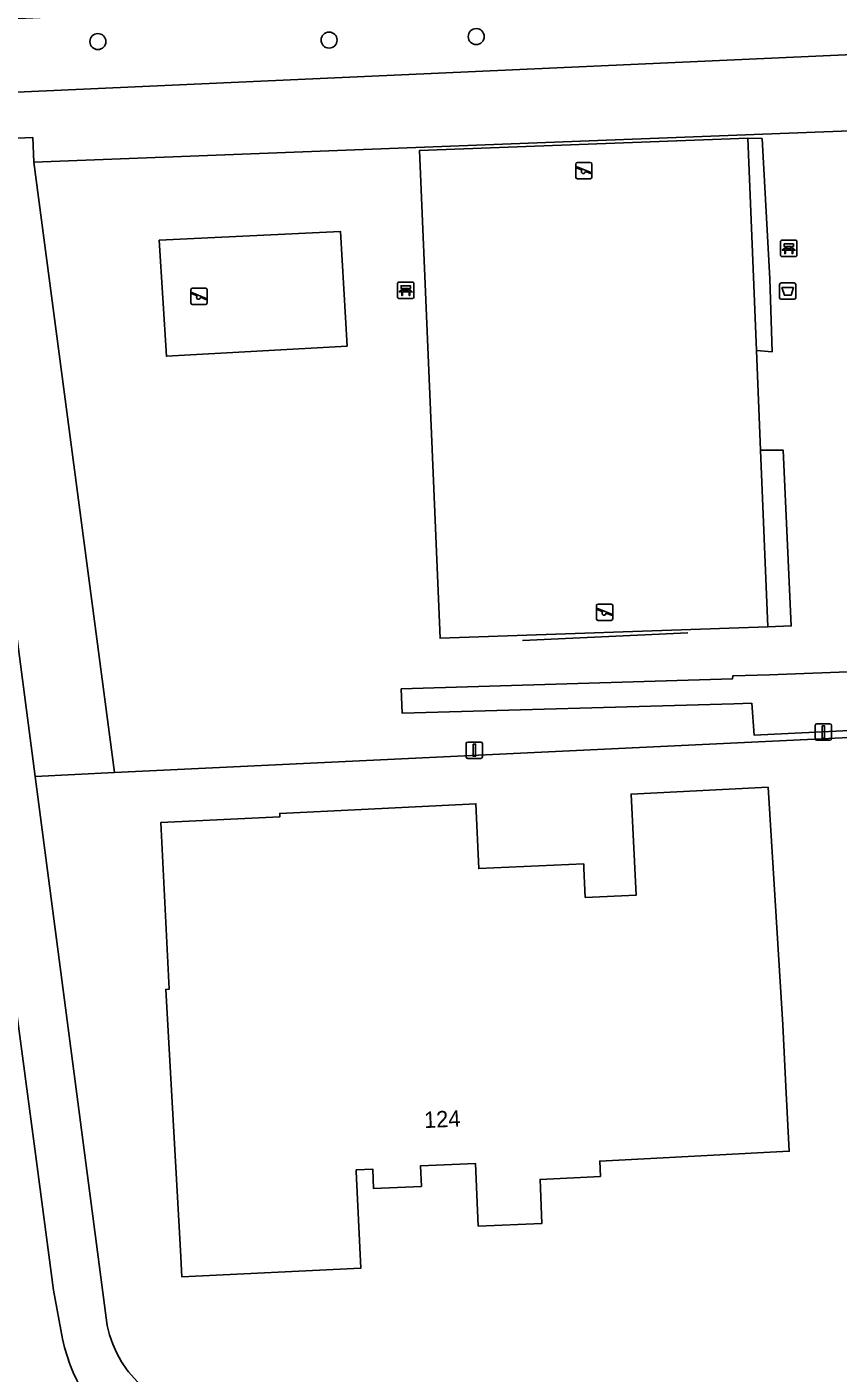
# Model space of a CAD drawing. Extents: x 161084 to 161928, y 385354 to 386522.
# Drawn here: x 161207.1 to 161256.7, y 385753.3 to 385835.6 of the extents above; entities that cross this region are included whole.
import ezdxf

# ---------------------------------------------------------------- set-up
doc = ezdxf.new("R2010")
doc.units = 0
for name, color, linetype in [('IMGEO_Afvalbak', 7, 'Continuous'), ('IMGEO_Bank', 7, 'Continuous'), ('IMGEO_Boom', 7, 'Continuous'), ('IMGEO_Erf', 7, 'Continuous'), ('IMGEO_Fietspad_gesloten', 7, 'Continuous'), ('IMGEO_Groenvoorziening', 7, 'Continuous'), ('IMGEO_Hek', 7, 'Continuous'), ('IMGEO_Lichtmast', 7, 'Continuous'), ('IMGEO_Pand', 7, 'Continuous'), ('IMGEO_Pand_nummerreeks', 7, 'Continuous'), ('IMGEO_Speelvoorziening', 7, 'Continuous'), ('IMGEO_Terreindeel_gesloten', 7, 'Continuous'), ('IMGEO_Terreindeel_onvherhard', 7, 'Continuous'), ('IMGEO_Voetpad_open', 7, 'Continuous')]:
    doc.layers.add(name, color=color, linetype=linetype)

msp = doc.modelspace()

# ---------------------------------------------------------------- linework, layer by layer
at = {"layer": 'IMGEO_Afvalbak'}
for p, q in [((161253.102, 385819.03), (161253.102, 385819.83)), ((161253.102, 385819.83), (161253.102, 385819.03)), ((161253.202, 385819.93), (161253.992, 385819.93)), ((161253.992, 385819.93), (161253.202, 385819.93)), ((161254.092, 385819.83), (161254.092, 385819.03)), ((161254.092, 385819.03), (161254.092, 385819.83)), ((161253.992, 385818.93), (161253.202, 385818.93)), ((161253.202, 385818.93), (161253.992, 385818.93))]:
    msp.add_line(p, q, dxfattribs=at)
msp.add_lwpolyline([(161253.245, 385819.644), (161253.949, 385819.644), (161253.8, 385819.174), (161253.394, 385819.174), (161253.245, 385819.644)], dxfattribs=at)
for centre, start, end in [((161253.202, 385819.83), 90, 180), ((161253.202, 385819.83), 90, 180), ((161253.992, 385819.83), 0, 90), ((161253.992, 385819.83), 360, 90), ((161253.202, 385819.03), 180, 270), ((161253.202, 385819.03), 180, 270), ((161253.992, 385819.03), 270, 0), ((161253.992, 385819.03), 270, 0)]:
    msp.add_arc(centre, 0.1, start, end, dxfattribs=at)
at = {"layer": 'IMGEO_Bank'}
for p, q in [((161253.161, 385821.616), (161253.161, 385822.457)), ((161253.161, 385822.457), (161253.161, 385821.616)), ((161253.236, 385822.541), (161254.077, 385822.541)), ((161254.077, 385822.541), (161253.236, 385822.541)), ((161253.858, 385821.939), (161253.465, 385821.939)), ((161253.47, 385822.047), (161253.47, 385822.153)), ((161253.514, 385822.153), (161253.514, 385822.047)), ((161253.802, 385822.159), (161253.52, 385822.159)), ((161253.52, 385822.041), (161253.802, 385822.041)), ((161253.808, 385822.047), (161253.808, 385822.153)), ((161253.852, 385822.153), (161253.852, 385822.047)), ((161254.161, 385822.466), (161254.161, 385821.625)), ((161254.161, 385821.625), (161254.161, 385822.466)), ((161254.086, 385821.541), (161253.245, 385821.541)), ((161253.245, 385821.541), (161254.086, 385821.541)), ((161229.73, 385819.057), (161229.73, 385819.898)), ((161229.73, 385819.898), (161229.73, 385819.057)), ((161229.805, 385819.982), (161230.646, 385819.982)), ((161230.646, 385819.982), (161229.805, 385819.982)), ((161230.039, 385819.488), (161230.039, 385819.594)), ((161230.083, 385819.594), (161230.083, 385819.488)), ((161230.371, 385819.6), (161230.089, 385819.6)), ((161230.089, 385819.482), (161230.371, 385819.482)), ((161230.377, 385819.488), (161230.377, 385819.594)), ((161230.421, 385819.594), (161230.421, 385819.488)), ((161230.73, 385819.907), (161230.73, 385819.066)), ((161230.73, 385819.066), (161230.73, 385819.907)), ((161230.655, 385818.982), (161229.814, 385818.982)), ((161229.814, 385818.982), (161230.655, 385818.982)), ((161230.427, 385819.38), (161230.034, 385819.38))]:
    msp.add_line(p, q, dxfattribs=at)
for points in [[(161253.408, 385821.939), (161253.266, 385821.939), (161253.378, 385822.041), (161253.464, 385822.041)], [(161253.464, 385822.159), (161253.378, 385822.159), (161253.378, 385822.32), (161253.941, 385822.32), (161253.941, 385822.159), (161253.858, 385822.159)], [(161253.458, 385821.932), (161253.458, 385821.725), (161253.415, 385821.725), (161253.415, 385821.932)], [(161253.858, 385822.041), (161253.941, 385822.041), (161254.053, 385821.939), (161253.914, 385821.939)], [(161253.908, 385821.932), (161253.908, 385821.725), (161253.864, 385821.725), (161253.864, 385821.932)], [(161229.977, 385819.38), (161229.835, 385819.38), (161229.947, 385819.482), (161230.033, 385819.482)], [(161230.033, 385819.6), (161229.947, 385819.6), (161229.947, 385819.761), (161230.51, 385819.761), (161230.51, 385819.6), (161230.427, 385819.6)], [(161230.427, 385819.482), (161230.51, 385819.482), (161230.622, 385819.38), (161230.483, 385819.38)], [(161230.027, 385819.373), (161230.027, 385819.166), (161229.984, 385819.166), (161229.984, 385819.373)], [(161230.477, 385819.373), (161230.477, 385819.166), (161230.433, 385819.166), (161230.433, 385819.373)]]:
    msp.add_lwpolyline(points, dxfattribs=at)
for centre, radius, start, end in [((161253.239, 385822.463), 0.0779, 92.4484, 184.28452), ((161253.239, 385822.463), 0.0779, 92.4484, 184.28452), ((161253.408, 385821.932), 0.00671, 2.89567, 87.10433), ((161253.465, 385821.932), 0.00671, 92.89567, 177.10433), ((161253.463, 385822.152), 0.00671, 2.89567, 87.10433), ((161253.463, 385822.048), 0.00671, 272.89567, 357.10433), ((161253.52, 385822.152), 0.00671, 92.89567, 177.10433), ((161253.52, 385822.048), 0.00671, 182.89567, 267.10433), ((161253.802, 385822.152), 0.00671, 2.89567, 87.10433), ((161253.802, 385822.048), 0.00671, 272.89567, 357.10433), ((161253.859, 385822.152), 0.00671, 92.89567, 177.10433), ((161253.859, 385822.048), 0.00671, 182.89567, 267.10433), ((161253.857, 385821.932), 0.00671, 2.89567, 87.10433), ((161253.914, 385821.932), 0.00671, 92.89567, 177.10433), ((161254.083, 385822.463), 0.0779, 2.4484, 94.28452), ((161254.083, 385822.463), 0.0779, 2.4484, 94.28452), ((161253.239, 385821.619), 0.0779, 182.4484, 274.28452), ((161253.239, 385821.619), 0.0779, 182.4484, 274.28452), ((161254.083, 385821.619), 0.0779, 272.4484, 4.28452), ((161254.083, 385821.619), 0.0779, 272.4484, 4.28452), ((161229.808, 385819.904), 0.0779, 92.4484, 184.28452), ((161229.808, 385819.904), 0.0779, 92.4484, 184.28452), ((161230.032, 385819.593), 0.00671, 2.89567, 87.10433), ((161230.032, 385819.489), 0.00671, 272.89567, 357.10433), ((161230.089, 385819.593), 0.00671, 92.89567, 177.10433), ((161230.089, 385819.489), 0.00671, 182.89567, 267.10433), ((161230.371, 385819.593), 0.00671, 2.89567, 87.10433), ((161230.371, 385819.489), 0.00671, 272.89567, 357.10433), ((161230.428, 385819.593), 0.00671, 92.89567, 177.10433), ((161230.428, 385819.489), 0.00671, 182.89567, 267.10433), ((161230.652, 385819.904), 0.0779, 2.4484, 94.28452), ((161230.652, 385819.904), 0.0779, 2.4484, 94.28452), ((161229.808, 385819.06), 0.0779, 182.4484, 274.28452), ((161229.808, 385819.06), 0.0779, 182.4484, 274.28452), ((161229.977, 385819.373), 0.00671, 2.89567, 87.10433), ((161230.034, 385819.373), 0.00671, 92.89567, 177.10433), ((161230.426, 385819.373), 0.00671, 2.89567, 87.10433), ((161230.483, 385819.373), 0.00671, 92.89567, 177.10433), ((161230.652, 385819.06), 0.0779, 272.4484, 4.28452), ((161230.652, 385819.06), 0.0779, 272.4484, 4.28452)]:
    msp.add_arc(centre, radius, start, end, dxfattribs=at)
at = {"layer": 'IMGEO_Boom'}
for centre in [(161211.394, 385834.688), (161225.538, 385834.781), (161234.541, 385834.99)]:
    msp.add_circle(centre, 0.489, dxfattribs=at)
at = {"layer": 'IMGEO_Erf'}
msp.add_lwpolyline([(161272.857, 385792.894), (161255.66, 385792.058), (161212.404, 385789.993), (161207.561, 385789.762), (161211.966, 385756.196), (161212.108, 385755.611), (161212.302, 385755.04), (161212.546, 385754.49), (161212.838, 385753.963), (161213.176, 385753.465), (161213.26, 385753.354), (161214.348, 385752.155)], dxfattribs=at)
msp.add_lwpolyline([(161234.664, 385762.266), (161234.497, 385766.092), (161231.128, 385765.946), (161231.182, 385764.692), (161228.259, 385764.563), (161228.206, 385765.755), (161227.197, 385765.706), (161227.202, 385765.606), (161227.486, 385759.696), (161216.52, 385759.168), (161216.441, 385760.775), (161215.546, 385776.741), (161215.746, 385776.751), (161215.241, 385786.94), (161222.534, 385787.299), (161222.524, 385787.498), (161227.518, 385787.744), (161234.52, 385788.09), (161234.695, 385784.122), (161241.117, 385784.406), (161241.129, 385784.12), (161241.207, 385782.36), (161244.322, 385782.491), (161244.015, 385788.683), (161252.394, 385789.097), (161253.303, 385774.578), (161253.484, 385770.805), (161253.689, 385766.848), (161244.045, 385766.345), (161242.098, 385766.243), (161242.133, 385765.306), (161238.447, 385765.122), (161238.469, 385764.583), (161238.557, 385762.435)], close=True, dxfattribs=at)
at = {"layer": 'IMGEO_Fietspad_gesloten'}
msp.add_lwpolyline([(161209.233, 385755.378), (161208.683, 385758.357), (161207.529, 385766.988), (161203.904, 385794.069)], dxfattribs=at)
msp.add_arc((161219.815, 385757.617), 10.816, 191.94693, 237.44684, dxfattribs=at)
at = {"layer": 'IMGEO_Groenvoorziening'}
for points in [[(161278.406, 385834.825), (161278.27, 385839.356), (161201.511, 385835.864), (161202.461, 385828.626), (161204.969, 385828.722), (161204.604, 385831.503)], [(161278.406, 385834.825), (161204.604, 385831.503), (161204.969, 385828.722), (161207.416, 385828.815), (161207.473, 385827.316), (161252.603, 385829.039), (161275.084, 385829.897), (161278.756, 385829.729)], [(161276.948, 385796.915), (161280.478, 385797.085), (161278.756, 385829.729), (161275.084, 385829.897), (161252.603, 385829.039), (161207.473, 385827.316), (161212.404, 385789.993), (161255.66, 385792.058), (161272.857, 385792.894), (161272.85, 385793.331), (161251.543, 385792.29), (161251.394, 385794.229), (161250.306, 385794.194), (161230.001, 385793.63), (161229.95, 385795.109), (161250.223, 385795.729), (161250.244, 385795.918), (161252.491, 385795.977)], [(161212.404, 385789.993), (161207.473, 385827.316), (161207.416, 385828.815), (161204.969, 385828.722), (161202.461, 385828.626), (161207.561, 385789.762)], [(161231.074, 385828.031), (161251.149, 385828.784), (161252.028, 385828.761), (161252.494, 385820.183), (161252.649, 385815.719), (161251.684, 385815.798), (161251.936, 385809.7), (161253.324, 385809.7), (161253.81, 385798.965), (161252.381, 385798.901), (161232.329, 385798.205)], [(161251.149, 385828.784), (161251.684, 385815.798), (161252.649, 385815.719), (161252.494, 385820.183), (161252.028, 385828.761)], [(161215.589, 385815.449), (161215.147, 385822.541), (161226.24, 385823.075), (161226.642, 385816.069)], [(161252.381, 385798.901), (161253.81, 385798.965), (161253.324, 385809.7), (161251.936, 385809.7)]]:
    msp.add_lwpolyline(points, close=True, dxfattribs=at)
at = {"layer": 'IMGEO_Hek'}
for points in [[(161252.603, 385829.039), (161275.084, 385829.897)], [(161207.473, 385827.316), (161252.603, 385829.039)], [(161212.404, 385789.993), (161207.473, 385827.316)], [(161247.495, 385798.546), (161237.365, 385798.075)], [(161255.66, 385792.058), (161272.857, 385792.894)], [(161255.66, 385792.058), (161212.404, 385789.993)], [(161212.404, 385789.993), (161207.561, 385789.762)]]:
    msp.add_lwpolyline(points, dxfattribs=at)
at = {"layer": 'IMGEO_Lichtmast'}
for p, q in [((161255.286, 385792.074), (161255.286, 385792.874)), ((161255.286, 385792.874), (161255.286, 385792.074)), ((161255.386, 385792.974), (161256.176, 385792.974)), ((161256.176, 385792.974), (161255.386, 385792.974)), ((161256.276, 385792.874), (161256.276, 385792.074)), ((161256.276, 385792.074), (161256.276, 385792.874)), ((161233.926, 385790.964), (161233.926, 385791.764)), ((161233.926, 385791.764), (161233.926, 385790.964)), ((161234.026, 385791.864), (161234.816, 385791.864)), ((161234.816, 385791.864), (161234.026, 385791.864)), ((161234.916, 385791.764), (161234.916, 385790.964)), ((161234.916, 385790.964), (161234.916, 385791.764)), ((161256.176, 385791.974), (161255.386, 385791.974)), ((161255.386, 385791.974), (161256.176, 385791.974)), ((161234.816, 385790.864), (161234.026, 385790.864)), ((161234.026, 385790.864), (161234.816, 385790.864))]:
    msp.add_line(p, q, dxfattribs=at)
for points in [[(161255.706, 385792.849), (161255.856, 385792.849), (161255.856, 385792.099), (161255.706, 385792.099), (161255.706, 385792.849)], [(161234.346, 385791.739), (161234.496, 385791.739), (161234.496, 385790.989), (161234.346, 385790.989), (161234.346, 385791.739)]]:
    msp.add_lwpolyline(points, dxfattribs=at)
for centre, start, end in [((161255.386, 385792.874), 90, 180), ((161255.386, 385792.874), 90, 180), ((161256.176, 385792.874), 0, 90), ((161256.176, 385792.874), 360, 90), ((161234.026, 385791.764), 90, 180), ((161234.026, 385791.764), 90, 180), ((161234.816, 385791.764), 0, 90), ((161234.816, 385791.764), 360, 90), ((161255.386, 385792.074), 180, 270), ((161255.386, 385792.074), 180, 270), ((161256.176, 385792.074), 270, 0), ((161256.176, 385792.074), 270, 0), ((161234.026, 385790.964), 180, 270), ((161234.026, 385790.964), 180, 270), ((161234.816, 385790.964), 270, 0), ((161234.816, 385790.964), 270, 0)]:
    msp.add_arc(centre, 0.1, start, end, dxfattribs=at)
at = {"layer": 'IMGEO_Pand'}
msp.add_lwpolyline([(161253.303, 385774.578), (161252.394, 385789.097), (161244.015, 385788.683), (161244.322, 385782.491), (161241.207, 385782.36), (161241.129, 385784.12), (161241.117, 385784.406), (161234.695, 385784.122), (161234.52, 385788.09), (161227.518, 385787.744), (161222.524, 385787.498), (161222.534, 385787.299), (161215.241, 385786.94), (161215.746, 385776.751), (161215.546, 385776.741), (161216.441, 385760.775), (161216.52, 385759.168), (161227.486, 385759.696), (161227.202, 385765.606), (161227.197, 385765.706), (161228.206, 385765.755), (161228.259, 385764.563), (161231.182, 385764.692), (161231.128, 385765.946), (161234.497, 385766.092), (161234.664, 385762.266), (161238.557, 385762.435), (161238.469, 385764.583), (161238.447, 385765.122), (161242.133, 385765.306), (161242.098, 385766.243), (161244.045, 385766.345), (161253.689, 385766.848), (161253.484, 385770.805)], close=True, dxfattribs=at)
at = {"layer": 'IMGEO_Speelvoorziening'}
for p, q in [((161240.629, 385826.401), (161240.629, 385827.201)), ((161240.629, 385827.201), (161240.629, 385826.401)), ((161241.012, 385826.829), (161240.673, 385826.966)), ((161240.698, 385827.026), (161241.574, 385826.673)), ((161240.729, 385827.301), (161241.519, 385827.301)), ((161241.519, 385827.301), (161240.729, 385827.301)), ((161241.619, 385827.201), (161241.619, 385826.401)), ((161241.619, 385826.401), (161241.619, 385827.201)), ((161241.519, 385826.301), (161240.729, 385826.301)), ((161240.729, 385826.301), (161241.519, 385826.301)), ((161241.55, 385826.613), (161241.21, 385826.75)), ((161217.082, 385818.711), (161217.082, 385819.511)), ((161217.082, 385819.511), (161217.082, 385818.711)), ((161217.182, 385819.611), (161217.972, 385819.611)), ((161217.972, 385819.611), (161217.182, 385819.611)), ((161218.072, 385819.511), (161218.072, 385818.711)), ((161218.072, 385818.711), (161218.072, 385819.511)), ((161217.465, 385819.139), (161217.126, 385819.276)), ((161217.151, 385819.336), (161218.027, 385818.983)), ((161217.972, 385818.611), (161217.182, 385818.611)), ((161217.182, 385818.611), (161217.972, 385818.611)), ((161218.003, 385818.923), (161217.663, 385819.06)), ((161241.898, 385799.4), (161241.898, 385800.2)), ((161241.898, 385800.2), (161241.898, 385799.4)), ((161242.281, 385799.828), (161241.942, 385799.965)), ((161241.967, 385800.025), (161242.843, 385799.672)), ((161241.998, 385800.3), (161242.788, 385800.3)), ((161242.788, 385800.3), (161241.998, 385800.3)), ((161242.819, 385799.612), (161242.479, 385799.749)), ((161242.888, 385800.2), (161242.888, 385799.4)), ((161242.888, 385799.4), (161242.888, 385800.2)), ((161242.788, 385799.3), (161241.998, 385799.3)), ((161241.998, 385799.3), (161242.788, 385799.3))]:
    msp.add_line(p, q, dxfattribs=at)
for centre, radius, start, end in [((161240.729, 385827.201), 0.1, 90, 180), ((161240.729, 385827.201), 0.1, 90, 180), ((161240.686, 385826.996), 0.0327, 68.07798, 248.07798), ((161241.091, 385826.739), 0.12, 130.99278, 5.16318), ((161241.519, 385827.201), 0.1, 0, 90), ((161241.519, 385827.201), 0.1, 360, 90), ((161240.729, 385826.401), 0.1, 180, 270), ((161240.729, 385826.401), 0.1, 180, 270), ((161241.519, 385826.401), 0.1, 270, 0), ((161241.519, 385826.401), 0.1, 270, 0), ((161241.562, 385826.643), 0.0327, 248.07798, 68.07798), ((161217.182, 385819.511), 0.1, 90, 180), ((161217.182, 385819.511), 0.1, 90, 180), ((161217.972, 385819.511), 0.1, 0, 90), ((161217.972, 385819.511), 0.1, 360, 90), ((161217.182, 385818.711), 0.1, 180, 270), ((161217.182, 385818.711), 0.1, 180, 270), ((161217.139, 385819.306), 0.0327, 68.07798, 248.07798), ((161217.544, 385819.049), 0.12, 130.99278, 5.16318), ((161217.972, 385818.711), 0.1, 270, 0), ((161217.972, 385818.711), 0.1, 270, 0), ((161218.015, 385818.953), 0.0327, 248.07798, 68.07798), ((161241.998, 385800.2), 0.1, 90, 180), ((161241.998, 385800.2), 0.1, 90, 180), ((161241.955, 385799.995), 0.0327, 68.07798, 248.07798), ((161242.36, 385799.738), 0.12, 130.99278, 5.16318), ((161242.788, 385800.2), 0.1, 0, 90), ((161242.788, 385800.2), 0.1, 360, 90), ((161242.831, 385799.642), 0.0327, 248.07798, 68.07798), ((161241.998, 385799.4), 0.1, 180, 270), ((161241.998, 385799.4), 0.1, 180, 270), ((161242.788, 385799.4), 0.1, 270, 0), ((161242.788, 385799.4), 0.1, 270, 0)]:
    msp.add_arc(centre, radius, start, end, dxfattribs=at)
at = {"layer": 'IMGEO_Terreindeel_gesloten'}
msp.add_lwpolyline([(161251.684, 385815.798), (161251.149, 385828.784), (161231.074, 385828.031), (161232.329, 385798.205), (161252.381, 385798.901), (161251.936, 385809.7)], close=True, dxfattribs=at)
at = {"layer": 'IMGEO_Terreindeel_onvherhard'}
msp.add_lwpolyline([(161226.642, 385816.069), (161226.24, 385823.075), (161215.147, 385822.541), (161215.589, 385815.449)], close=True, dxfattribs=at)
at = {"layer": 'IMGEO_Voetpad_open'}
for points in [[(161214.348, 385752.155), (161213.26, 385753.354), (161213.176, 385753.465), (161212.838, 385753.963), (161212.546, 385754.49), (161212.302, 385755.04), (161212.108, 385755.611), (161211.966, 385756.196), (161207.561, 385789.762), (161202.461, 385828.626), (161201.511, 385835.864), (161200.876, 385840.705), (161200.484, 385843.768), (161198.739, 385856.928), (161198.436, 385859.257), (161196.387, 385874.969), (161195.995, 385877.316), (161193.899, 385892.906), (161193.638, 385895.214), (161191.516, 385910.725), (161191.332, 385912.99), (161189.272, 385928.602)], [(161203.904, 385794.069), (161207.529, 385766.988), (161208.683, 385758.357), (161209.233, 385755.378)]]:
    msp.add_lwpolyline(points, dxfattribs=at)
msp.add_lwpolyline([(161280.478, 385797.085), (161276.948, 385796.915), (161252.491, 385795.977), (161250.244, 385795.918), (161250.223, 385795.729), (161229.95, 385795.109), (161230.001, 385793.63), (161250.306, 385794.194), (161251.394, 385794.229), (161251.543, 385792.29), (161272.85, 385793.331), (161275.728, 385793.277), (161277.886, 385793.367), (161280.699, 385793.514)], close=True, dxfattribs=at)
msp.add_arc((161219.815, 385757.617), 10.816, 191.94693, 237.44684, dxfattribs=at)

# ---------------------------------------------------------------- texts
at = {"layer": 'IMGEO_Pand_nummerreeks'}
msp.add_text('124', height=1, rotation=2.5382, dxfattribs=at).set_placement((161231.368, 385768.258))

doc.saveas('drawing.dxf')
